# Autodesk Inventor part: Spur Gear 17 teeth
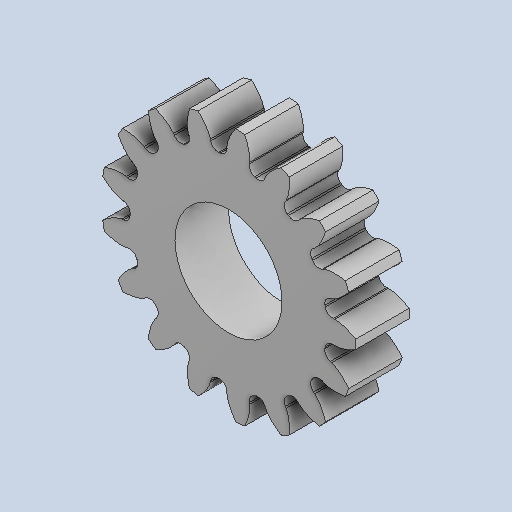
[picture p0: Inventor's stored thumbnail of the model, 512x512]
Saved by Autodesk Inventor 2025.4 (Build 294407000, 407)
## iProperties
Created: 2026-05
Part Number: Spur Gear 17 teeth
Material: Generic
Description: Spur Gear; Module: 1.0; Num Teeth: 17; Pressure Angle: 20.0; Backlash: 0.00 mm
Document SubType Name: Modeling
Designer: AdminForWorker
Density: 1 g/cm^3
Appearance: Default
Title: Spur Gear 17 teeth
Author: AdminForWorker
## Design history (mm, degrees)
feature "Body1"
body "Solid1"
